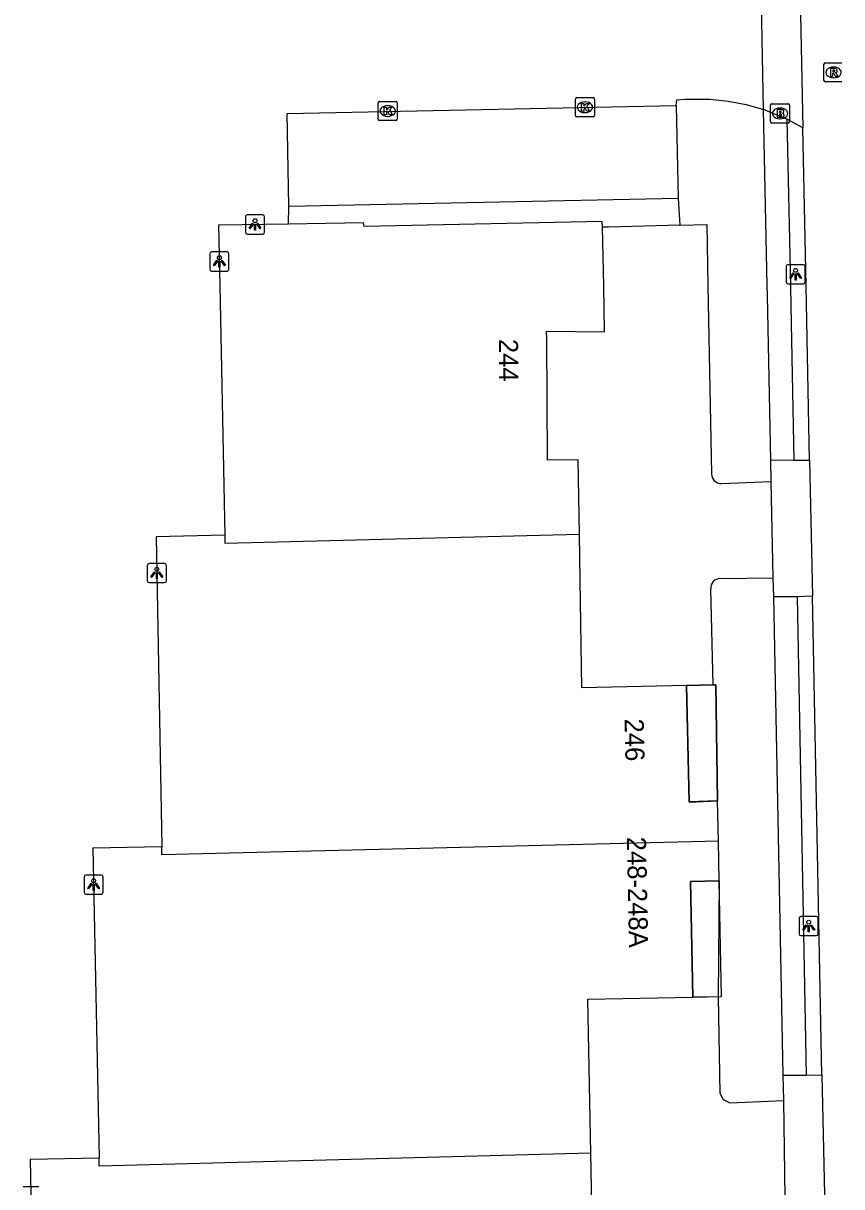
# Model space of a CAD drawing. Extents: x 161389 to 162585, y 388479 to 389761.
# Drawn here: x 162450.4 to 162493.2, y 388952.9 to 389013.7 of the extents above; entities that cross this region are included whole.
import ezdxf

# ---------------------------------------------------------------- set-up
doc = ezdxf.new("R2010")
doc.units = 0
for name, color, linetype in [('IMGEO_Brandkraan', 7, 'Continuous'), ('IMGEO_Groenvoorziening', 7, 'Continuous'), ('IMGEO_Kolk', 7, 'Continuous'), ('IMGEO_Lichtpunt', 7, 'Continuous'), ('IMGEO_Pand', 7, 'Continuous'), ('IMGEO_Pand_nummerreeks', 7, 'Continuous'), ('IMGEO_Pand_overbouw', 7, 'Continuous'), ('IMGEO_Parkeervlak_open', 7, 'Continuous'), ('IMGEO_Rijbaan_lokaal_gesloten', 7, 'Continuous'), ('IMGEO_Rijbaan_lokaal_open', 7, 'Continuous'), ('IMGEO_Rioolput', 7, 'Continuous'), ('IMGEO_Voetpad_open', 7, 'Continuous')]:
    doc.layers.add(name, color=color, linetype=linetype)

msp = doc.modelspace()

# ---------------------------------------------------------------- linework, layer by layer
at = {"layer": 'IMGEO_Brandkraan'}
for p, q in [((162489.536, 389009.503), (162490.388, 389009.503)), ((162489.461, 389008.577), (162489.461, 389009.429)), ((162489.949, 389009.283), (162489.974, 389009.283)), ((162490.462, 389009.429), (162490.462, 389008.577)), ((162490.388, 389008.503), (162489.536, 389008.503)), ((162489.972, 389008.723), (162489.947, 389008.723))]:
    msp.add_line(p, q, dxfattribs=at)
for points in [[(162489.536, 389009.503), (162490.388, 389009.503)], [(162489.461, 389008.577), (162489.461, 389009.429)], [(162489.809, 389009.203), (162489.809, 389008.803), (162490.022, 389008.803)], [(162490.04, 389009.203), (162489.809, 389009.203)], [(162489.988, 389009.122), (162489.934, 389009.122), (162489.934, 389009.046)], [(162489.934, 389009.046), (162489.987, 389009.046)], [(162489.996, 389008.97), (162489.934, 389008.97), (162489.934, 389008.889)], [(162489.934, 389008.889), (162489.996, 389008.889)], [(162490.462, 389009.429), (162490.462, 389008.577)], [(162490.388, 389008.503), (162489.536, 389008.503)]]:
    msp.add_lwpolyline(points, dxfattribs=at)
for centre, radius, start, end in [((162489.538, 389009.427), 0.0765, 91.55205, 178.44795), ((162489.538, 389009.427), 0.0765, 91.55205, 178.44795), ((162490.386, 389009.427), 0.0765, 1.55205, 88.44795), ((162490.386, 389009.427), 0.0765, 1.55205, 88.44795), ((162489.989, 389009.084), 0.0379, 267.82845, 90.93552), ((162489.997, 389008.929), 0.0404, 269.87594, 90.50774), ((162490.028, 389009.054), 0.251, 268.66757, 293.53466), ((162490.044, 389009.058), 0.145, 59.4692, 91.53667), ((162490.069, 389009.105), 0.0922, 285.51372, 58.15012), ((162490.074, 389008.913), 0.105, 301.31148, 78.98903), ((162489.538, 389008.579), 0.0765, 181.55205, 268.44795), ((162489.538, 389008.579), 0.0765, 181.55205, 268.44795), ((162490.386, 389008.579), 0.0765, 271.55205, 358.44795), ((162490.386, 389008.579), 0.0765, 271.55205, 358.44795)]:
    msp.add_arc(centre, radius, start, end, dxfattribs=at)
for centre, major_axis, ratio, start_param, end_param in [((162489.948, 389009.003), (-0.387, 0.002), 0.722429, 4.712389, 7.853982), ((162489.973, 389009.003), (-0.39, 0.002), 0.717154, 1.570796, 4.712389)]:
    msp.add_ellipse(centre, major_axis=major_axis, ratio=ratio, start_param=start_param, end_param=end_param, dxfattribs=at)
at = {"layer": 'IMGEO_Groenvoorziening'}
for points in [[(162486.474, 388979.141), (162486.603, 388979.144), (162486.699, 388973.085)], [(162486.781, 388968.908), (162486.738, 388962.839)]]:
    msp.add_lwpolyline(points, dxfattribs=at)
at = {"layer": 'IMGEO_Kolk'}
for p, q in [((162468.969, 389008.704), (162468.969, 389009.556)), ((162469.044, 389009.63), (162469.896, 389009.63)), ((162469.97, 389009.556), (162469.97, 389008.704)), ((162479.271, 389008.903), (162479.271, 389009.755)), ((162479.346, 389009.829), (162480.198, 389009.829)), ((162479.759, 389009.609), (162479.784, 389009.609)), ((162480.272, 389009.755), (162480.272, 389008.903)), ((162469.48, 389008.85), (162469.455, 389008.85)), ((162469.457, 389009.41), (162469.482, 389009.41)), ((162480.198, 389008.829), (162479.346, 389008.829)), ((162479.782, 389009.049), (162479.757, 389009.049)), ((162469.896, 389008.63), (162469.044, 389008.63))]:
    msp.add_line(p, q, dxfattribs=at)
for points in [[(162468.969, 389008.704), (162468.969, 389009.556)], [(162469.044, 389009.63), (162469.896, 389009.63)], [(162469.97, 389009.556), (162469.97, 389008.704)], [(162479.271, 389008.903), (162479.271, 389009.755)], [(162479.346, 389009.829), (162480.198, 389009.829)], [(162479.592, 389009.529), (162479.715, 389009.529), (162479.715, 389009.378), (162479.845, 389009.529), (162480.009, 389009.529), (162479.863, 389009.378), (162480.016, 389009.129), (162479.864, 389009.129), (162479.779, 389009.293), (162479.715, 389009.226), (162479.715, 389009.129), (162479.592, 389009.129), (162479.592, 389009.529)], [(162480.272, 389009.755), (162480.272, 389008.903)], [(162469.29, 389009.33), (162469.413, 389009.33), (162469.413, 389009.179), (162469.543, 389009.33), (162469.707, 389009.33), (162469.561, 389009.179), (162469.714, 389008.93), (162469.562, 389008.93), (162469.477, 389009.094), (162469.413, 389009.027), (162469.413, 389008.93), (162469.29, 389008.93), (162469.29, 389009.33)], [(162480.198, 389008.829), (162479.346, 389008.829)], [(162469.896, 389008.63), (162469.044, 389008.63)]]:
    msp.add_lwpolyline(points, dxfattribs=at)
for centre, start, end in [((162469.046, 389009.554), 91.55205, 178.44795), ((162469.046, 389009.554), 91.55205, 178.44795), ((162469.894, 389009.554), 1.55205, 88.44795), ((162469.894, 389009.554), 1.55205, 88.44795), ((162479.348, 389009.753), 91.55205, 178.44795), ((162479.348, 389009.753), 91.55205, 178.44795), ((162480.196, 389009.753), 1.55205, 88.44795), ((162480.196, 389009.753), 1.55205, 88.44795), ((162479.348, 389008.905), 181.55205, 268.44795), ((162479.348, 389008.905), 181.55205, 268.44795), ((162480.196, 389008.905), 271.55205, 358.44795), ((162480.196, 389008.905), 271.55205, 358.44795), ((162469.046, 389008.706), 181.55205, 268.44795), ((162469.046, 389008.706), 181.55205, 268.44795), ((162469.894, 389008.706), 271.55205, 358.44795), ((162469.894, 389008.706), 271.55205, 358.44795)]:
    msp.add_arc(centre, 0.0765, start, end, dxfattribs=at)
for centre, major_axis, ratio, start_param, end_param in [((162479.758, 389009.329), (-0.387, 0.002), 0.722429, 4.712389, 7.853982), ((162479.783, 389009.329), (-0.39, 0.002), 0.717154, 1.570796, 4.712389), ((162469.456, 389009.13), (-0.387, 0.002), 0.722429, 4.712389, 7.853982), ((162469.481, 389009.13), (-0.39, 0.002), 0.717154, 1.570796, 4.712389)]:
    msp.add_ellipse(centre, major_axis=major_axis, ratio=ratio, start_param=start_param, end_param=end_param, dxfattribs=at)
at = {"layer": 'IMGEO_Lichtpunt'}
for p, q in [((162462.039, 389003.602), (162462.039, 389002.795)), ((162462.039, 389003.602), (162462.039, 389002.795)), ((162462.941, 389003.697), (162462.133, 389003.697)), ((162462.941, 389003.697), (162462.133, 389003.697)), ((162463.035, 389002.795), (162463.035, 389003.602)), ((162463.035, 389002.795), (162463.035, 389003.602)), ((162462.133, 389002.701), (162462.941, 389002.701)), ((162462.133, 389002.701), (162462.941, 389002.701)), ((162460.177, 389001.669), (162460.177, 389000.862)), ((162460.177, 389001.669), (162460.177, 389000.862)), ((162461.079, 389001.764), (162460.271, 389001.764)), ((162461.079, 389001.764), (162460.271, 389001.764)), ((162461.173, 389000.862), (162461.173, 389001.669)), ((162461.173, 389000.862), (162461.173, 389001.669)), ((162490.278, 389001.003), (162490.278, 389000.196)), ((162490.278, 389001.003), (162490.278, 389000.196)), ((162491.18, 389001.098), (162490.372, 389001.098)), ((162491.18, 389001.098), (162490.372, 389001.098)), ((162491.274, 389000.196), (162491.274, 389001.003)), ((162491.274, 389000.196), (162491.274, 389001.003)), ((162460.271, 389000.768), (162461.079, 389000.768)), ((162460.271, 389000.768), (162461.079, 389000.768)), ((162490.372, 389000.102), (162491.18, 389000.102)), ((162490.372, 389000.102), (162491.18, 389000.102)), ((162456.91, 388985.388), (162456.91, 388984.581)), ((162456.91, 388985.388), (162456.91, 388984.581)), ((162457.812, 388985.483), (162457.004, 388985.483)), ((162457.812, 388985.483), (162457.004, 388985.483)), ((162457.906, 388984.581), (162457.906, 388985.388)), ((162457.906, 388984.581), (162457.906, 388985.388)), ((162457.004, 388984.487), (162457.812, 388984.487)), ((162457.004, 388984.487), (162457.812, 388984.487)), ((162453.611, 388969.113), (162453.611, 388968.306)), ((162453.611, 388969.113), (162453.611, 388968.306)), ((162454.513, 388969.208), (162453.705, 388969.208)), ((162454.513, 388969.208), (162453.705, 388969.208)), ((162454.607, 388968.306), (162454.607, 388969.113)), ((162454.607, 388968.306), (162454.607, 388969.113)), ((162453.705, 388968.212), (162454.513, 388968.212)), ((162453.705, 388968.212), (162454.513, 388968.212)), ((162490.96, 388966.949), (162490.96, 388966.142)), ((162490.96, 388966.949), (162490.96, 388966.142)), ((162491.862, 388967.044), (162491.054, 388967.044)), ((162491.862, 388967.044), (162491.054, 388967.044)), ((162491.956, 388966.142), (162491.956, 388966.949)), ((162491.956, 388966.142), (162491.956, 388966.949)), ((162491.054, 388966.048), (162491.862, 388966.048)), ((162491.054, 388966.048), (162491.862, 388966.048)), ((162451.241, 388952.923), (162450.433, 388952.923)), ((162451.241, 388952.923), (162450.433, 388952.923))]:
    msp.add_line(p, q, dxfattribs=at)
for points in [[(162462.413, 389003.266), (162462.452, 389003.238), (162462.264, 389002.976), (162462.226, 389003.003), (162462.413, 389003.266)], [(162462.515, 389003.218), (162462.562, 389003.218), (162462.562, 389002.896), (162462.515, 389002.896), (162462.515, 389003.218)], [(162462.625, 389003.238), (162462.663, 389003.265), (162462.85, 389003.003), (162462.811, 389002.975), (162462.625, 389003.238)], [(162460.551, 389001.333), (162460.59, 389001.305), (162460.402, 389001.043), (162460.364, 389001.07), (162460.551, 389001.333)], [(162460.653, 389001.285), (162460.7, 389001.285), (162460.7, 389000.963), (162460.653, 389000.963), (162460.653, 389001.285)], [(162460.763, 389001.305), (162460.801, 389001.332), (162460.988, 389001.07), (162460.949, 389001.042), (162460.763, 389001.305)], [(162490.652, 389000.667), (162490.691, 389000.639), (162490.503, 389000.377), (162490.465, 389000.404), (162490.652, 389000.667)], [(162490.754, 389000.619), (162490.801, 389000.619), (162490.801, 389000.297), (162490.754, 389000.297), (162490.754, 389000.619)], [(162490.864, 389000.639), (162490.902, 389000.666), (162491.089, 389000.404), (162491.05, 389000.376), (162490.864, 389000.639)], [(162457.284, 388985.052), (162457.323, 388985.024), (162457.135, 388984.762), (162457.097, 388984.789), (162457.284, 388985.052)], [(162457.386, 388985.004), (162457.433, 388985.004), (162457.433, 388984.682), (162457.386, 388984.682), (162457.386, 388985.004)], [(162457.496, 388985.024), (162457.534, 388985.051), (162457.721, 388984.789), (162457.682, 388984.761), (162457.496, 388985.024)], [(162453.985, 388968.777), (162454.024, 388968.749), (162453.836, 388968.487), (162453.798, 388968.514), (162453.985, 388968.777)], [(162454.087, 388968.729), (162454.134, 388968.729), (162454.134, 388968.407), (162454.087, 388968.407), (162454.087, 388968.729)], [(162454.197, 388968.749), (162454.235, 388968.776), (162454.422, 388968.514), (162454.383, 388968.486), (162454.197, 388968.749)], [(162491.334, 388966.613), (162491.373, 388966.585), (162491.185, 388966.323), (162491.147, 388966.35), (162491.334, 388966.613)], [(162491.436, 388966.565), (162491.483, 388966.565), (162491.483, 388966.243), (162491.436, 388966.243), (162491.436, 388966.565)], [(162491.546, 388966.585), (162491.584, 388966.612), (162491.771, 388966.35), (162491.732, 388966.322), (162491.546, 388966.585)]]:
    msp.add_lwpolyline(points, dxfattribs=at)
for centre in [(162462.538, 389003.4), (162460.676, 389001.467), (162490.777, 389000.801), (162457.409, 388985.186), (162454.11, 388968.911), (162491.459, 388966.747)]:
    msp.add_circle(centre, 0.0994, dxfattribs=at)
for centre, start, end in [((162462.133, 389003.602), 90, 180), ((162462.133, 389003.602), 90, 180), ((162462.941, 389003.602), 0, 90), ((162462.941, 389003.602), 0, 90), ((162462.133, 389002.795), 180, 270), ((162462.133, 389002.795), 180, 270), ((162462.941, 389002.795), 270, 0), ((162462.941, 389002.795), 270, 360), ((162460.271, 389001.669), 90, 180), ((162460.271, 389001.669), 90, 180), ((162461.079, 389001.669), 0, 90), ((162461.079, 389001.669), 0, 90), ((162490.372, 389001.003), 90, 180), ((162490.372, 389001.003), 90, 180), ((162491.18, 389001.003), 0, 90), ((162491.18, 389001.003), 0, 90), ((162460.271, 389000.862), 180, 270), ((162460.271, 389000.862), 180, 270), ((162461.079, 389000.862), 270, 0), ((162461.079, 389000.862), 270, 360), ((162490.372, 389000.196), 180, 270), ((162490.372, 389000.196), 180, 270), ((162491.18, 389000.196), 270, 0), ((162491.18, 389000.196), 270, 360), ((162457.004, 388985.388), 90, 180), ((162457.004, 388985.388), 90, 180), ((162457.812, 388985.388), 0, 90), ((162457.812, 388985.388), 0, 90), ((162457.004, 388984.581), 180, 270), ((162457.004, 388984.581), 180, 270), ((162457.812, 388984.581), 270, 0), ((162457.812, 388984.581), 270, 360), ((162453.705, 388969.113), 90, 180), ((162453.705, 388969.113), 90, 180), ((162454.513, 388969.113), 0, 90), ((162454.513, 388969.113), 0, 90), ((162453.705, 388968.306), 180, 270), ((162453.705, 388968.306), 180, 270), ((162454.513, 388968.306), 270, 0), ((162454.513, 388968.306), 270, 360), ((162491.054, 388966.949), 90, 180), ((162491.054, 388966.949), 90, 180), ((162491.862, 388966.949), 0, 90), ((162491.862, 388966.949), 0, 90), ((162491.054, 388966.142), 180, 270), ((162491.054, 388966.142), 180, 270), ((162491.862, 388966.142), 270, 0), ((162491.862, 388966.142), 270, 360)]:
    msp.add_arc(centre, 0.0946, start, end, dxfattribs=at)
at = {"layer": 'IMGEO_Pand'}
for points in [[(162480.686, 389003.06), (162480.674, 389003.356), (162468.234, 389003.089), (162468.211, 389003.295), (162464.289, 389003.224)], [(162464.289, 389003.224), (162460.632, 389003.165), (162460.695, 389000), (162460.953, 388986.972)], [(162479.488, 388987.019), (162479.426, 388990.908), (162477.816, 388990.882), (162477.779, 388997.231), (162477.763, 388997.625), (162480.8, 388997.593), (162480.75, 389000), (162480.686, 389003.06)], [(162460.953, 388986.972), (162457.367, 388986.884), (162457.669, 388970.682)], [(162460.953, 388986.972), (162460.961, 388986.552), (162479.488, 388987.019)], [(162485.082, 388979.109), (162479.607, 388978.991), (162479.527, 388984.617), (162479.488, 388987.019)], [(162486.699, 388973.085), (162485.22, 388973.029), (162485.082, 388979.109)], [(162486.74, 388970.982), (162486.699, 388973.085)], [(162457.669, 388970.682), (162454.065, 388970.609), (162454.396, 388954.421)], [(162486.74, 388970.982), (162457.677, 388970.262), (162457.669, 388970.682)], [(162486.781, 388968.908), (162486.74, 388970.982)], [(162485.411, 388962.828), (162485.287, 388968.877), (162486.781, 388968.908)], [(162480.076, 388954.684), (162479.919, 388962.732), (162485.411, 388962.828)], [(162454.396, 388954.421), (162450.794, 388954.344), (162451.11, 388938.136)], [(162480.076, 388954.684), (162454.405, 388954.001), (162454.396, 388954.421)], [(162485.687, 388946.726), (162480.234, 388946.617), (162480.076, 388954.684)]]:
    msp.add_lwpolyline(points, dxfattribs=at)
at = {"layer": 'IMGEO_Pand_overbouw'}
for points in [[(162486.603, 388979.144), (162486.474, 388979.141), (162485.082, 388979.109), (162485.22, 388973.018), (162486.699, 388973.085)], [(162486.781, 388968.908), (162485.287, 388968.877), (162485.411, 388962.828), (162486.901, 388962.854)]]:
    msp.add_lwpolyline(points, close=True, dxfattribs=at)
at = {"layer": 'IMGEO_Parkeervlak_open'}
for points in [[(162484.537, 389009.425), (162484.639, 389004.582)], [(162484.722, 389003.167), (162486.131, 389003.204), (162486.193, 389000), (162486.383, 388990.175)], [(162486.89, 388989.661), (162489.504, 388989.767)], [(162486.835, 388984.698), (162489.607, 388984.73)], [(162486.474, 388979.141), (162486.34, 388984.168)], [(162485.082, 388979.109), (162486.474, 388979.141)], [(162486.738, 388962.839), (162485.411, 388962.828)], [(162486.738, 388962.839), (162486.818, 388957.815), (162486.995, 388957.473), (162487.344, 388957.311), (162490.163, 388957.43)]]:
    msp.add_lwpolyline(points, dxfattribs=at)
for centre, radius, start, end in [((162486.887, 388990.165), 0.504, 178.83452, 270.37985), ((162486.83, 388984.206), 0.492, 89.45796, 184.4534)]:
    msp.add_arc(centre, radius, start, end, dxfattribs=at)
at = {"layer": 'IMGEO_Rijbaan_lokaal_gesloten'}
for points in [[(162490.951, 389018.401), (162491.156, 389008.259)], [(162491.505, 388990.892), (162491.322, 389000), (162491.156, 389008.259)], [(162491.505, 388990.892), (162491.649, 388983.772)], [(162492.152, 388958.778), (162491.649, 388983.772)], [(162492.152, 388958.778), (162492.294, 388951.732)]]:
    msp.add_lwpolyline(points, dxfattribs=at)
at = {"layer": 'IMGEO_Rijbaan_lokaal_open'}
for points in [[(162489.105, 389009.202), (162488.94, 389017.541)], [(162484.537, 389009.425), (162484.565, 389009.708), (162485.013, 389009.74), (162485.342, 389009.756), (162486.298, 389009.744), (162487.248, 389009.648), (162488.187, 389009.466), (162489.105, 389009.202)], [(162464.312, 389004.165), (162464.21, 389009.005), (162484.537, 389009.425)], [(162464.289, 389003.224), (162464.312, 389004.165)]]:
    msp.add_lwpolyline(points, dxfattribs=at)
at = {"layer": 'IMGEO_Rioolput'}
for p, q in [((162492.257, 389010.722), (162492.257, 389011.574)), ((162492.332, 389011.648), (162493.184, 389011.648)), ((162492.745, 389011.428), (162492.77, 389011.428)), ((162493.184, 389010.648), (162492.332, 389010.648)), ((162492.768, 389010.868), (162492.743, 389010.868))]:
    msp.add_line(p, q, dxfattribs=at)
for points in [[(162492.257, 389010.722), (162492.257, 389011.574)], [(162492.332, 389011.648), (162493.184, 389011.648)], [(162492.846, 389011.346), (162492.594, 389011.348), (162492.594, 389010.948)], [(162492.772, 389011.267), (162492.718, 389011.267), (162492.718, 389011.186)], [(162493.184, 389010.648), (162492.332, 389010.648)], [(162492.594, 389010.948), (162492.718, 389010.948), (162492.718, 389011.11), (162492.729, 389011.11)], [(162492.718, 389011.186), (162492.77, 389011.186)], [(162492.776, 389011.081), (162492.847, 389010.948), (162492.987, 389010.948), (162492.922, 389011.074)]]:
    msp.add_lwpolyline(points, dxfattribs=at)
for centre, radius, start, end in [((162492.334, 389011.572), 0.0765, 91.55205, 178.44795), ((162492.334, 389011.572), 0.0765, 91.55205, 178.44795), ((162492.778, 389011.171), 0.0964, 77.00612, 93.18647), ((162492.792, 389011.228), 0.0378, 276.66336, 79.67722), ((162492.845, 389011.236), 0.109, 350.36119, 89.41601), ((162492.334, 389010.724), 0.0765, 181.55205, 268.44795), ((162492.334, 389010.724), 0.0765, 181.55205, 268.44795), ((162492.728, 389011.057), 0.0533, 26.02933, 88.69889), ((162492.754, 389011.375), 0.19, 274.7715, 282.96867), ((162492.843, 389011.236), 0.112, 277.58423, 350.98172), ((162492.827, 389011.021), 0.108, 29.51342, 73.79051)]:
    msp.add_arc(centre, radius, start, end, dxfattribs=at)
for centre, major_axis, ratio, start_param, end_param in [((162492.744, 389011.148), (-0.387, 0.002), 0.722429, 4.712389, 7.853982), ((162492.769, 389011.148), (-0.39, 0.002), 0.717154, 1.570796, 4.712389)]:
    msp.add_ellipse(centre, major_axis=major_axis, ratio=ratio, start_param=start_param, end_param=end_param, dxfattribs=at)
at = {"layer": 'IMGEO_Voetpad_open'}
for points in [[(162489.482, 388990.868), (162489.306, 388999.491), (162489.295, 389000), (162489.105, 389009.202)], [(162490.312, 389008.711), (162489.105, 389009.202)], [(162491.156, 389008.259), (162490.312, 389008.711)], [(162490.312, 389008.711), (162490.501, 389000), (162490.524, 388998.957), (162490.684, 388990.89)], [(162464.312, 389004.165), (162484.639, 389004.582)], [(162484.639, 389004.582), (162484.722, 389003.167)], [(162484.722, 389003.167), (162481.01, 389003.069), (162480.686, 389003.06)], [(162490.684, 388990.89), (162489.482, 388990.868)], [(162489.504, 388989.767), (162489.482, 388990.868)], [(162490.684, 388990.89), (162491.505, 388990.892)], [(162489.607, 388984.73), (162489.504, 388989.767)], [(162489.634, 388983.74), (162489.607, 388984.73)], [(162490.848, 388983.753), (162489.634, 388983.74)], [(162490.121, 388958.751), (162489.634, 388983.74)], [(162491.649, 388983.772), (162490.848, 388983.753)], [(162490.848, 388983.753), (162491.33, 388958.751)], [(162490.163, 388957.43), (162490.121, 388958.751)], [(162490.121, 388958.751), (162491.33, 388958.751)], [(162491.33, 388958.751), (162492.152, 388958.778)], [(162490.236, 388952.36), (162490.163, 388957.43)]]:
    msp.add_lwpolyline(points, dxfattribs=at)

# ---------------------------------------------------------------- texts
at = {"layer": 'IMGEO_Pand_nummerreeks'}
for s, rotation, p in [('244', 270.33211, (162475.279, 388997.219)), ('246', 271.30024, (162481.84, 388977.373)), ('248-248A', 271.17436, (162481.959, 388971.201))]:
    msp.add_text(s, height=1, rotation=rotation, dxfattribs=at).set_placement(p)

doc.saveas('drawing.dxf')
